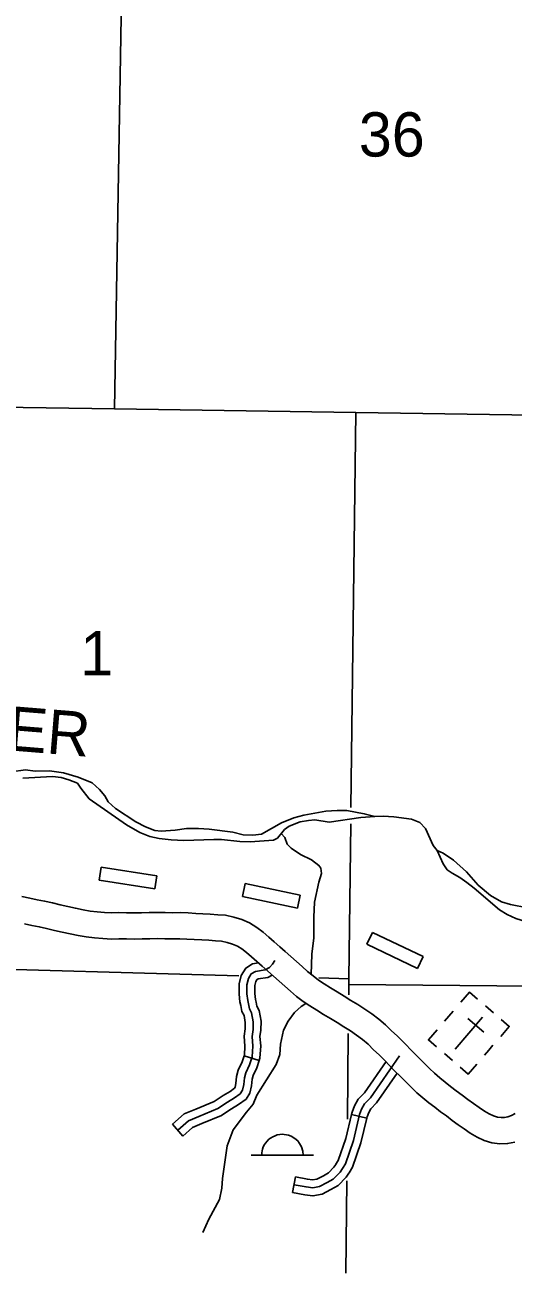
# Model space of a CAD drawing. Extents: x 0 to 3171, y 0 to 2059.
# Drawn here: x 1303 to 1380.6, y 456.9 to 655.3 of the extents above; entities that cross this region are included whole.
import ezdxf

# ---------------------------------------------------------------- set-up
doc = ezdxf.new("R2010")
doc.units = 0
for name, color, linetype in [('Level 10', 7, 'Continuous'), ('Level 35', 7, 'Continuous'), ('Level 4', 7, 'Continuous'), ('Level 45', 7, 'Continuous'), ('Level 5', 7, 'Continuous'), ('Level 57', 7, 'Continuous')]:
    doc.layers.add(name, color=color, linetype=linetype)

msp = doc.modelspace()

# ---------------------------------------------------------------- linework, layer by layer
at = {"layer": 'Level 10'}
for points in [[(1302.5, 516.74), (1303.75, 516.5), (1304.94, 516.24), (1306.12, 516.01), (1307.39, 515.72), (1308.61, 515.41), (1309.79, 515.16), (1311.02, 514.89), (1312.22, 514.65), (1313.37, 514.44), (1314.48, 514.3), (1315.61, 514.22), (1316.82, 514.16), (1317.89, 514.18), (1319.14, 514.17), (1320.35, 514.16), (1321.54, 514.17), (1322.75, 514.2), (1324.03, 514.22), (1325.3, 514.18), (1326.45, 514.17), (1327.65, 514.2), (1328.95, 514.15), (1330.15, 514.06), (1331.27, 514.01), (1332.46, 513.96), (1333.63, 513.86), (1334.85, 513.77), (1336.19, 513.48), (1337.45, 513.09), (1338.69, 512.54), (1339.84, 511.84), (1340.84, 511.06), (1341.74, 510.3), (1342.61, 509.54), (1343.49, 508.77), (1344.38, 507.98), (1345.27, 507.2), (1346.17, 506.4), (1347.07, 505.61), (1347.94, 504.84), (1348.8, 504.12), (1349.66, 503.46), (1350.58, 502.84), (1351.58, 502.21), (1352.64, 501.57), (1353.72, 500.91), (1354.81, 500.24), (1355.91, 499.56), (1357.01, 498.85), (1358.14, 498.09), (1359.25, 497.25), (1360.33, 496.34), (1361.29, 495.42), (1362.17, 494.59), (1363.03, 493.76), (1364.89, 491.83), (1365.64, 491.08), (1366.47, 490.24), (1367.3, 489.42), (1368.12, 488.64), (1368.94, 487.92), (1369.79, 487.23), (1370.67, 486.55), (1371.56, 485.88), (1372.49, 485.19), (1373.42, 484.49), (1374.32, 483.83), (1375.2, 483.2), (1376.04, 482.62), (1376.79, 482.18), (1377.49, 481.86), (1378.12, 481.67), (1378.69, 481.6), (1379.23, 481.62), (1379.78, 481.73), (1380.34, 481.93), (1380.95, 482.23)], [(1380.9, 477.71), (1379.74, 477.47), (1378.51, 477.42), (1377.24, 477.58), (1376.02, 477.95), (1374.87, 478.47), (1373.79, 479.11), (1372.81, 479.79), (1371.88, 480.45), (1370.93, 481.15), (1369.99, 481.86), (1369.07, 482.54), (1368.14, 483.24), (1367.2, 483.96), (1366.25, 484.73), (1365.31, 485.56), (1364.4, 486.43), (1363.53, 487.28), (1362.68, 488.14), (1361.77, 489.05), (1360.22, 490.68), (1359.29, 491.58), (1358.42, 492.4), (1357.54, 493.25), (1356.65, 494), (1355.72, 494.69), (1354.73, 495.37), (1353.68, 496.03), (1352.62, 496.7), (1351.55, 497.36), (1350.47, 498.01), (1349.39, 498.67), (1348.31, 499.35), (1347.23, 500.08), (1346.19, 500.87), (1345.22, 501.68), (1344.31, 502.48), (1343.41, 503.28), (1342.51, 504.07), (1341.61, 504.87), (1340.73, 505.65), (1339.87, 506.41), (1339.02, 507.14), (1338.21, 507.83), (1337.47, 508.41), (1336.76, 508.84), (1335.99, 509.18), (1335.12, 509.45), (1334.25, 509.64), (1333.31, 509.71), (1332.2, 509.8), (1331.09, 509.85), (1329.9, 509.9), (1328.71, 509.99), (1327.62, 510.03), (1326.48, 510), (1325.21, 510.01), (1323.99, 510.06), (1322.83, 510.04), (1321.61, 510.01), (1320.36, 509.99), (1319.11, 510.01), (1317.91, 510.01), (1316.75, 509.99), (1315.36, 510.07), (1314.07, 510.16), (1312.74, 510.32), (1311.43, 510.55), (1310.16, 510.82), (1308.92, 511.08), (1307.66, 511.35), (1306.41, 511.67), (1305.26, 511.94), (1304.1, 512.16), (1302.91, 512.42)]]:
    msp.add_lwpolyline(points, dxfattribs=at)
at = {"layer": 'Level 35'}
for points in [[(1300.77, 536.58), (1303.1, 536.87), (1304.59, 536.67), (1306.88, 536.75), (1309.14, 536.4), (1311.44, 535.72), (1313.67, 534.84), (1314.85, 533.77), (1315.67, 532.76), (1316.21, 531.8), (1317.36, 530.75), (1320.63, 528.63), (1322.17, 527.82), (1323.65, 527.26), (1324.65, 527.16), (1326.87, 527.3), (1328.69, 527.58), (1330.6, 527.56), (1332.27, 527.44), (1336.02, 526.97), (1337.7, 526.55), (1339.2, 526.51), (1340.59, 526.68), (1343.77, 528.44), (1345.75, 529.27), (1347.35, 529.68), (1350.81, 530.29), (1352.64, 530.4), (1354.15, 530.4)], [(1302.64, 535.55), (1307.37, 535.82), (1308.74, 535.64), (1309.99, 535.28), (1311.32, 534.76), (1311.85, 533.95), (1313.2, 532.28), (1319.11, 528.15), (1321.23, 526.91), (1322.87, 526.31), (1324.34, 525.97), (1326.25, 525.73), (1328.26, 525.66), (1333.01, 525.83), (1334.22, 525.81), (1337.14, 525.48), (1338.79, 525.44), (1342.51, 525.7), (1343.15, 526.04), (1344.26, 527.38), (1345, 527.92), (1346.77, 528.63), (1348.05, 528.85)], [(1354.15, 530.4), (1356.94, 529.9), (1358.62, 529.46)], [(1348.05, 528.85), (1349.08, 528.91), (1351.35, 528.59), (1356.41, 529.31), (1358.62, 529.46)], [(1358.62, 529.46), (1359.92, 529.52), (1361.66, 529.4), (1364.44, 529.04), (1365.77, 528.51), (1366.69, 527.57), (1367.92, 524.83), (1368.54, 524.07)], [(1343.72, 526.76), (1344.31, 526.14), (1344.7, 525.06), (1345.32, 524.43), (1346.82, 523.43), (1348.57, 522.56), (1349.74, 521.7), (1350.03, 521.27), (1350.13, 520.38), (1349.69, 519.01), (1349.05, 515.83), (1348.9, 513.47), (1348.92, 510.18), (1348.58, 507.58), (1348.5, 504.35)], [(1418.83, 522.15), (1416.73, 520.05), (1413.85, 517.62), (1413.11, 517), (1409.37, 514.72), (1405.37, 512.69), (1402.09, 510.55), (1400.9, 509.94), (1398.96, 509.54), (1397.36, 509.85), (1394.66, 511.26), (1388.76, 512.36), (1386.17, 513.07), (1384.93, 513.78), (1383.86, 514.52), (1382.87, 514.96), (1380.17, 515.5), (1378.76, 515.92), (1377.01, 516.89), (1375.04, 518.56), (1373.2, 520.66), (1371.11, 522.53), (1369.46, 523.64), (1368.54, 524.07)], [(1368.54, 524.07), (1369.5, 521.95), (1370.12, 521.01), (1370.92, 520.45), (1372.14, 519.77), (1373.27, 518.96), (1374.43, 518.07), (1378.45, 514.62), (1379.67, 513.91), (1381.05, 513.25), (1387.59, 511.2), (1389.24, 510.79), (1393.13, 510.22), (1394.52, 509.8), (1396.99, 508.73), (1398.22, 508.44), (1399.42, 508.36), (1400.53, 508.62), (1401.94, 509.08), (1403.64, 509.88), (1410.29, 513.81), (1412.68, 515.68), (1414.65, 517.52), (1418.38, 520.75)], [(1347.67, 499.75), (1346.92, 499.24), (1345.86, 498.31), (1344.86, 496.94), (1344.12, 495.51), (1343.61, 493.26), (1343.51, 491.65), (1342.92, 490.06), (1339.88, 485.19), (1339.26, 483.74)], [(1339.26, 483.74), (1338.23, 482.49), (1336.11, 479.64), (1335.16, 477.12), (1334.42, 471.9), (1334.3, 470.38), (1333.93, 468.57), (1332.22, 465.48), (1331.29, 463.32)]]:
    msp.add_lwpolyline(points, dxfattribs=at)
at = {"layer": 'Level 4'}
for points in [[(1355.59, 593.71), (1317.21, 594.27), (1270, 594.95), (1244.78, 595.32)], [(1355.59, 593.71), (1354.82, 530.92)], [(1405.23, 592.96), (1355.59, 593.71)], [(1354.78, 528.28), (1354.48, 503.68), (1354.47, 502.77), (1354.46, 501.14)], [(1354.4, 494.99), (1354.26, 481.34)], [(1354.16, 471.56), (1354.01, 456.89)]]:
    msp.add_lwpolyline(points, dxfattribs=at)
at = {"layer": 'Level 45'}
for p, q in [((1340.23, 490.66), (1337.85, 491.42)), ((1328.1, 478.67), (1326.45, 480.55)), ((1357.33, 481.52), (1354.9, 482.09)), ((1345.54, 469.71), (1346.01, 472.16))]:
    msp.add_line(p, q, dxfattribs=at)
for points in [[(1327.27, 479.61), (1328.98, 481.1), (1330.63, 481.8), (1333.65, 483.07), (1335.17, 484.07), (1336.28, 484.72), (1337.21, 485.39), (1337.57, 485.96), (1337.78, 486.84), (1337.88, 487.92), (1338.09, 488.72), (1338.71, 489.99), (1339.12, 491.28), (1339.22, 492.97), (1339.09, 494.51), (1339.25, 495.62), (1339.27, 496.84), (1339.02, 498.23), (1338.68, 498.89), (1338.4, 500.21), (1338.29, 501.27), (1338.29, 502.71), (1338.52, 503.72), (1338.98, 504.45), (1339.63, 504.83), (1341.18, 505.09), (1341.87, 505.45), (1342.34, 505.99), (1342.73, 506.6)], [(1337.29, 499.43), (1337.16, 500.02), (1337.04, 501.2), (1337.03, 502.85), (1337.35, 504.21), (1338.09, 505.37), (1339.19, 506.03), (1340.12, 506.18)], [(1339.73, 499.95), (1339.63, 500.4), (1339.54, 501.33), (1339.54, 502.58), (1339.69, 503.23), (1339.88, 503.52), (1340.07, 503.64), (1341.58, 503.89), (1342.29, 504.26)], [(1337.85, 491.42), (1337.88, 491.51), (1337.97, 492.96), (1337.84, 494.55), (1338, 495.72), (1338.02, 496.74), (1337.82, 497.83), (1337.49, 498.47), (1337.29, 499.43)], [(1340.23, 490.66), (1340.36, 491.05), (1340.48, 492.99), (1340.35, 494.48), (1340.5, 495.52), (1340.53, 496.94), (1340.21, 498.64), (1339.87, 499.31), (1339.73, 499.95)], [(1334.18, 484.92), (1334.51, 485.14), (1335.6, 485.77), (1336.28, 486.26), (1336.4, 486.45), (1336.54, 487.04), (1336.65, 488.14), (1336.91, 489.16), (1337.54, 490.46), (1337.85, 491.42)], [(1335.56, 482.83), (1335.83, 483.01), (1336.96, 483.67), (1338.14, 484.52), (1338.74, 485.47), (1339.01, 486.63), (1339.12, 487.71), (1339.27, 488.29), (1339.87, 489.52), (1340.23, 490.66)], [(1345.78, 470.94), (1347.69, 470.57), (1348.74, 470.42), (1349.84, 470.64), (1351.03, 471.27), (1352.02, 471.82), (1353.1, 472.92), (1353.49, 473.51), (1353.95, 474.25), (1355.21, 477.95), (1356.19, 482.11), (1356.5, 482.92), (1356.97, 483.78), (1357.95, 484.74), (1362.55, 491.42)], [(1354.9, 482.09), (1354.99, 482.49), (1355.37, 483.45), (1355.96, 484.54), (1356.99, 485.54), (1360.41, 490.52)], [(1357.33, 481.52), (1357.38, 481.74), (1357.64, 482.39), (1357.98, 483.02), (1358.91, 483.93), (1362.17, 488.66)], [(1326.45, 480.55), (1328.3, 482.18), (1330.14, 482.95), (1333.06, 484.17), (1334.18, 484.92)], [(1328.1, 478.67), (1329.65, 480.03), (1331.11, 480.65), (1334.24, 481.96), (1335.56, 482.83)], [(1352.42, 474.15), (1352.44, 474.18), (1352.81, 474.79), (1354, 478.29), (1354.9, 482.09)], [(1354.5, 472.77), (1354.54, 472.83), (1355.09, 473.72), (1356.41, 477.6), (1357.33, 481.52)], [(1345.54, 469.71), (1347.48, 469.33), (1348.78, 469.15), (1350.26, 469.45), (1351.63, 470.17), (1352.79, 470.81), (1354.08, 472.13), (1354.5, 472.77)], [(1346.01, 472.16), (1347.89, 471.8), (1348.7, 471.69), (1349.42, 471.83), (1350.44, 472.37), (1351.26, 472.82), (1352.12, 473.71), (1352.42, 474.15)]]:
    msp.add_lwpolyline(points, dxfattribs=at)
at = {"layer": 'Level 5'}
for points in [[(1318.69, 681.53), (1317.21, 594.27)], [(1336.97, 504.16), (1288.23, 505.49)], [(1354.48, 503.68), (1349.69, 503.82)], [(1354.47, 502.77), (1430.95, 502.08)]]:
    msp.add_lwpolyline(points, dxfattribs=at)
at = {"layer": 'Level 57'}
for p, q in [((1315.1, 521.43), (1314.78, 519.37)), ((1323.95, 520.05), (1315.1, 521.43)), ((1323.63, 517.99), (1323.95, 520.05)), ((1314.78, 519.37), (1323.63, 517.99)), ((1338.01, 518.81), (1337.57, 516.77)), ((1346.77, 516.94), (1338.01, 518.81)), ((1337.57, 516.77), (1346.33, 514.9)), ((1346.33, 514.9), (1346.77, 516.94)), ((1358.23, 511.05), (1357.34, 509.17)), ((1366.33, 507.21), (1358.23, 511.05)), ((1357.34, 509.17), (1365.43, 505.32)), ((1365.43, 505.32), (1366.33, 507.21)), ((1371.08, 498.52), (1369.72, 496.94)), ((1377.47, 498.27), (1376.21, 499.35)), ((1375.74, 497.55), (1371.4, 492.49)), ((1373.39, 497.37), (1375.93, 495.19)), ((1373.57, 495.02), (1373.57, 495.02)), ((1373.57, 495.02), (1373.57, 495.02)), ((1376.73, 492.31), (1376.05, 491.51)), ((1376.73, 492.31), (1377.4, 493.09)), ((1369.69, 491.77), (1370.95, 490.68)), ((1338.98, 475.65), (1348.88, 475.65))]:
    msp.add_line(p, q, dxfattribs=at)
for points in [[(1374.93, 500.45), (1373.67, 501.53), (1372.31, 499.95)], [(1378.73, 497.19), (1379.99, 496.1), (1378.63, 494.52)], [(1368.42, 492.86), (1367.15, 493.95), (1368.51, 495.53)], [(1374.83, 490.1), (1373.48, 488.52), (1372.21, 489.6)]]:
    msp.add_lwpolyline(points, dxfattribs=at)
msp.add_lwpolyline([(1347.22, 475.65), (1347.16, 476.28), (1346.96, 476.95), (1346.66, 477.5), (1346.37, 477.9), (1345.9, 478.3), (1345.33, 478.65), (1344.87, 478.81), (1344.55, 478.88), (1344.2, 478.93), (1343.87, 478.95), (1343.51, 478.91), (1343.07, 478.84), (1342.75, 478.72), (1342.39, 478.56), (1342.03, 478.35), (1341.79, 478.15), (1341.48, 477.86), (1341.23, 477.55), (1341.08, 477.32), (1340.89, 476.97), (1340.75, 476.61), (1340.68, 476.34), (1340.64, 476.01), (1340.63, 475.65)], close=True, dxfattribs=at)

# ---------------------------------------------------------------- texts
at = {"layer": 'Level 35'}
msp.add_text('RIVER', height=7.04, rotation=355.3386, dxfattribs=at).set_placement((1284.39, 541.29))
at = {"layer": 'Level 5'}
for s, p in [('36', (1356.08, 634.37)), ('1', (1311.79, 551.9))]:
    msp.add_text(s, height=7.04, dxfattribs=at).set_placement(p)

doc.saveas('drawing.dxf')
